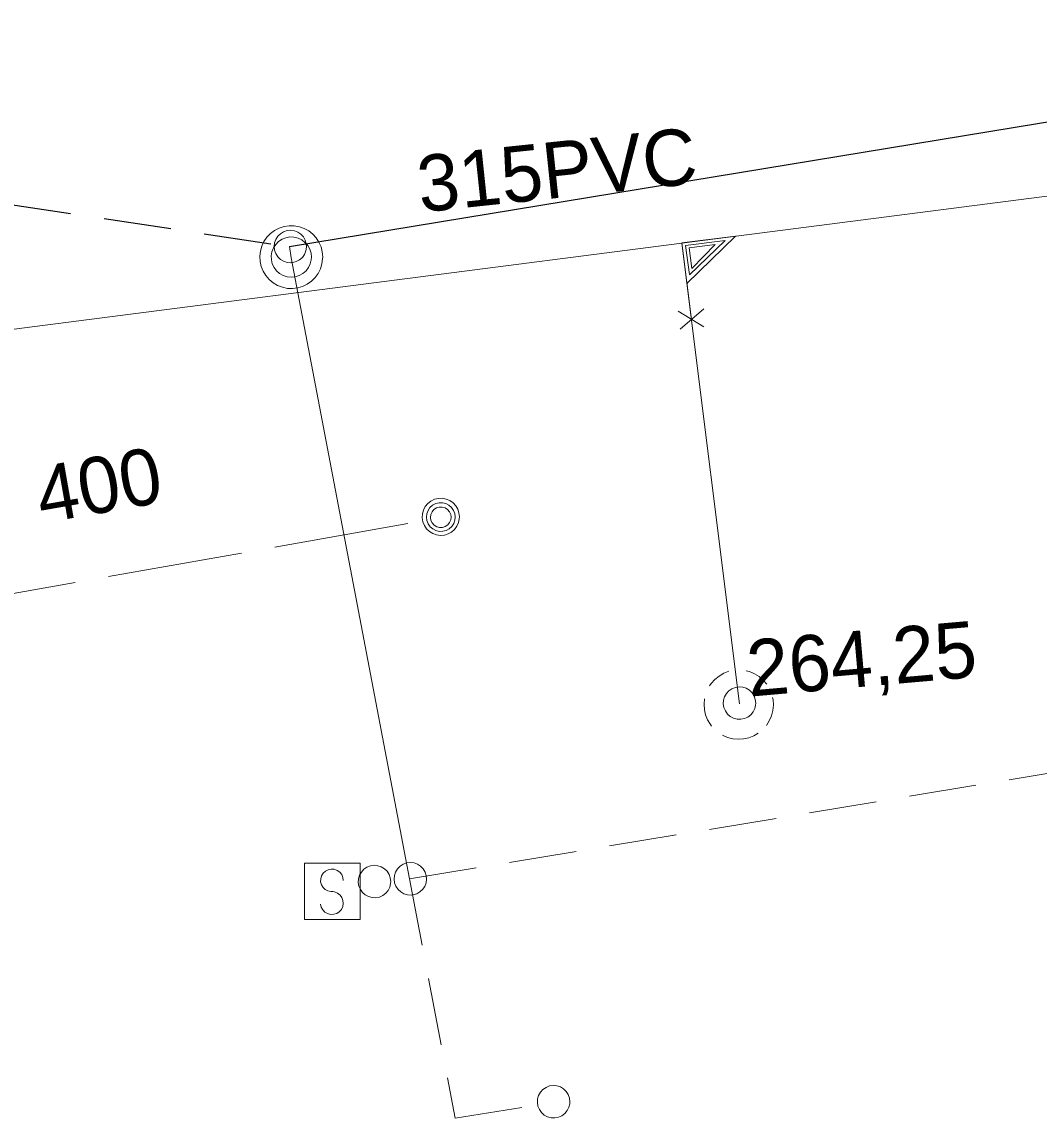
# Model space of a CAD drawing. Extents: x -732096 to -731933, y -1048703 to -1047964.
# Drawn here: x -732052.65 to -732038.19, y -1048400.1 to -1048384.52 of the extents above; entities that cross this region are included whole.
import ezdxf

# ---------------------------------------------------------------- set-up
doc = ezdxf.new("R2010")
doc.units = 0
doc.header["$LTSCALE"] = 0.32
doc.linetypes.add('LONG_DASHED', pattern=[7.5, 6, -1.5])
doc.linetypes.add('MEDIUM_DASHED', pattern=[4.5, 3, -1.5])
doc.layers.add('1', color=7, linetype='Continuous')
for name, color, linetype, lineweight in [('18', 7, 'Continuous', 13), ('20', 7, 'Continuous', 13), ('49', 7, 'Continuous', 13), ('8', 7, 'Continuous', 13)]:
    doc.layers.add(name, color=color, linetype=linetype, lineweight=lineweight)

msp = doc.modelspace()

# ---------------------------------------------------------------- linework, layer by layer
at = {"layer": '18'}
for p, q in [((-732042.954, -1048388.852), (-732043.32, -1048388.628)), ((-732043.29, -1048388.883), (-732042.954, -1048388.594))]:
    msp.add_line(p, q, dxfattribs=at)
for points in [[(-732043.129, -1048388.744), (-732043.269, -1048387.658), (-732042.505, -1048387.56), (-732043.195, -1048388.232)], [(-732043.161, -1048388.107), (-732043.214, -1048387.696), (-732042.652, -1048387.623), (-732043.16, -1048388.109)], [(-732042.602, -1048393.747), (-732042.673, -1048393.775), (-732042.74, -1048393.814), (-732042.8, -1048393.862), (-732042.851, -1048393.919), (-732042.875, -1048393.953)], [(-732042.061, -1048393.93), (-732042.111, -1048393.872), (-732042.169, -1048393.822), (-732042.234, -1048393.781), (-732042.305, -1048393.752), (-732042.354, -1048393.738)], [(-732042.066, -1048394.516), (-732042.025, -1048394.451), (-732041.994, -1048394.381), (-732041.975, -1048394.306), (-732041.967, -1048394.23), (-732041.972, -1048394.153), (-732041.978, -1048394.118)], [(-732042.947, -1048394.139), (-732042.953, -1048394.216), (-732042.948, -1048394.293), (-732042.931, -1048394.368), (-732042.902, -1048394.439), (-732042.862, -1048394.505), (-732042.846, -1048394.527)], [(-732042.689, -1048394.656), (-732042.619, -1048394.687), (-732042.544, -1048394.706), (-732042.468, -1048394.713), (-732042.391, -1048394.708), (-732042.316, -1048394.691), (-732042.244, -1048394.663), (-732042.184, -1048394.628)]]:
    msp.add_lwpolyline(points, dxfattribs=at)
for points in [[(-732043.125, -1048388.019), (-732043.162, -1048387.729), (-732042.793, -1048387.682)], [(-732046.43, -1048391.551), (-732046.436, -1048391.495), (-732046.453, -1048391.442), (-732046.482, -1048391.393), (-732046.52, -1048391.352), (-732046.566, -1048391.32), (-732046.618, -1048391.298), (-732046.673, -1048391.287), (-732046.729, -1048391.289), (-732046.784, -1048391.302), (-732046.835, -1048391.327), (-732046.879, -1048391.362), (-732046.915, -1048391.405), (-732046.94, -1048391.455), (-732046.955, -1048391.51), (-732046.958, -1048391.566), (-732046.949, -1048391.621), (-732046.928, -1048391.674), (-732046.897, -1048391.72), (-732046.857, -1048391.759), (-732046.809, -1048391.789), (-732046.756, -1048391.808), (-732046.7, -1048391.815), (-732046.644, -1048391.811), (-732046.59, -1048391.794), (-732046.541, -1048391.767), (-732046.499, -1048391.729), (-732046.466, -1048391.684), (-732046.443, -1048391.633), (-732046.431, -1048391.578)], [(-732046.489, -1048391.554), (-732046.495, -1048391.505), (-732046.513, -1048391.459), (-732046.541, -1048391.418), (-732046.578, -1048391.385), (-732046.622, -1048391.363), (-732046.67, -1048391.351), (-732046.719, -1048391.351), (-732046.767, -1048391.363), (-732046.811, -1048391.386), (-732046.848, -1048391.419), (-732046.876, -1048391.46), (-732046.893, -1048391.507), (-732046.899, -1048391.556), (-732046.892, -1048391.605), (-732046.874, -1048391.651), (-732046.846, -1048391.691), (-732046.809, -1048391.724), (-732046.765, -1048391.746), (-732046.716, -1048391.758), (-732046.667, -1048391.757), (-732046.619, -1048391.745), (-732046.576, -1048391.721), (-732046.539, -1048391.688), (-732046.511, -1048391.647), (-732046.495, -1048391.6)], [(-732046.548, -1048391.558), (-732046.554, -1048391.516), (-732046.571, -1048391.478), (-732046.599, -1048391.447), (-732046.634, -1048391.424), (-732046.674, -1048391.413), (-732046.716, -1048391.413), (-732046.756, -1048391.425), (-732046.791, -1048391.448), (-732046.818, -1048391.48), (-732046.835, -1048391.518), (-732046.84, -1048391.559), (-732046.834, -1048391.601), (-732046.816, -1048391.638), (-732046.788, -1048391.67), (-732046.752, -1048391.692), (-732046.712, -1048391.703), (-732046.67, -1048391.702), (-732046.63, -1048391.689), (-732046.596, -1048391.666), (-732046.569, -1048391.633), (-732046.553, -1048391.595)], [(-732042.218, -1048394.199), (-732042.224, -1048394.147), (-732042.242, -1048394.097), (-732042.27, -1048394.053), (-732042.308, -1048394.016), (-732042.353, -1048393.989), (-732042.403, -1048393.973), (-732042.455, -1048393.968), (-732042.507, -1048393.975), (-732042.556, -1048393.994), (-732042.6, -1048394.024), (-732042.635, -1048394.063), (-732042.661, -1048394.108), (-732042.676, -1048394.159), (-732042.679, -1048394.211), (-732042.671, -1048394.263), (-732042.65, -1048394.311), (-732042.62, -1048394.354), (-732042.58, -1048394.389), (-732042.534, -1048394.413), (-732042.483, -1048394.427), (-732042.431, -1048394.429), (-732042.379, -1048394.419), (-732042.331, -1048394.397), (-732042.289, -1048394.365), (-732042.256, -1048394.325), (-732042.232, -1048394.278), (-732042.22, -1048394.227)]]:
    msp.add_lwpolyline(points, close=True, dxfattribs=at)
at = {"layer": '20', "linetype": 'LONG_DASHED'}
msp.add_line((-732053.78, -1048392.82), (-732046.694, -1048391.564), dxfattribs=at)
msp.add_line((-732053.78, -1048392.82), (-732046.694, -1048391.564), dxfattribs=at)
at = {"layer": '20'}
msp.add_lwpolyline([(-732058.87, -1048389.67), (-732043.269, -1048387.661), (-732032.557, -1048386.281), (-732028.59, -1048385.77)], dxfattribs=at)
msp.add_lwpolyline([(-732058.87, -1048389.67), (-732043.269, -1048387.661), (-732032.557, -1048386.281), (-732028.59, -1048385.77)], dxfattribs=at)
at = {"layer": '49'}
msp.add_line((-732042.449, -1048394.21), (-732043.269, -1048387.661), dxfattribs=at)
msp.add_line((-732042.449, -1048394.21), (-732043.269, -1048387.661), dxfattribs=at)
at = {"layer": '8', "lineweight": 25}
msp.add_line((-732048.844, -1048387.71), (-732024.987, -1048383.778), dxfattribs=at)
at = {"layer": '8', "linetype": 'MEDIUM_DASHED', "lineweight": 25}
msp.add_line((-732054.329, -1048386.88), (-732048.844, -1048387.71), dxfattribs=at)
at = {"layer": '8'}
for points in [[(-732048.372, -1048387.859), (-732048.379, -1048387.786), (-732048.397, -1048387.715), (-732048.426, -1048387.648), (-732048.465, -1048387.587), (-732048.514, -1048387.532), (-732048.571, -1048387.487), (-732048.636, -1048387.452), (-732048.705, -1048387.427), (-732048.777, -1048387.414), (-732048.85, -1048387.413), (-732048.923, -1048387.424), (-732048.992, -1048387.447), (-732049.056, -1048387.48), (-732049.115, -1048387.524), (-732049.166, -1048387.577), (-732049.208, -1048387.637), (-732049.239, -1048387.704), (-732049.259, -1048387.774), (-732049.267, -1048387.847), (-732049.262, -1048387.92), (-732049.247, -1048387.991), (-732049.22, -1048388.059), (-732049.181, -1048388.122), (-732049.134, -1048388.177), (-732049.078, -1048388.224), (-732049.014, -1048388.261), (-732048.946, -1048388.288), (-732048.875, -1048388.303), (-732048.801, -1048388.306), (-732048.728, -1048388.297), (-732048.659, -1048388.276), (-732048.593, -1048388.244), (-732048.532, -1048388.202), (-732048.48, -1048388.151), (-732048.438, -1048388.091), (-732048.404, -1048388.026), (-732048.384, -1048387.956), (-732048.374, -1048387.884)], [(-732048.534, -1048387.859), (-732048.539, -1048387.801), (-732048.558, -1048387.745), (-732048.585, -1048387.694), (-732048.625, -1048387.65), (-732048.671, -1048387.614), (-732048.723, -1048387.589), (-732048.781, -1048387.575), (-732048.84, -1048387.573), (-732048.897, -1048387.583), (-732048.951, -1048387.605), (-732049, -1048387.637), (-732049.041, -1048387.678), (-732049.073, -1048387.727), (-732049.095, -1048387.782), (-732049.105, -1048387.839), (-732049.103, -1048387.898), (-732049.09, -1048387.955), (-732049.065, -1048388.008), (-732049.029, -1048388.054), (-732048.985, -1048388.093), (-732048.933, -1048388.121), (-732048.877, -1048388.139), (-732048.82, -1048388.145), (-732048.762, -1048388.139), (-732048.706, -1048388.122), (-732048.654, -1048388.093), (-732048.61, -1048388.054), (-732048.576, -1048388.008), (-732048.551, -1048387.955), (-732048.536, -1048387.898)], [(-732048.799, -1048387.936), (-732048.748, -1048387.923), (-732048.701, -1048387.897), (-732048.662, -1048387.863), (-732048.631, -1048387.82), (-732048.611, -1048387.771), (-732048.603, -1048387.72), (-732048.606, -1048387.667), (-732048.62, -1048387.617), (-732048.646, -1048387.571), (-732048.683, -1048387.532), (-732048.726, -1048387.504), (-732048.775, -1048387.485), (-732048.828, -1048387.477), (-732048.879, -1048387.482), (-732048.93, -1048387.498), (-732048.974, -1048387.526), (-732049.012, -1048387.562), (-732049.041, -1048387.607), (-732049.057, -1048387.656), (-732049.064, -1048387.708), (-732049.058, -1048387.76), (-732049.04, -1048387.81), (-732049.011, -1048387.854), (-732048.973, -1048387.891), (-732048.929, -1048387.918), (-732048.879, -1048387.934), (-732048.827, -1048387.939)], [(-732048.63, -1048396.475), (-732047.841, -1048396.475), (-732047.841, -1048397.275), (-732048.63, -1048397.275)], [(-732047.406, -1048396.736), (-732047.412, -1048396.684), (-732047.429, -1048396.634), (-732047.458, -1048396.59), (-732047.496, -1048396.553), (-732047.541, -1048396.526), (-732047.591, -1048396.51), (-732047.643, -1048396.505), (-732047.695, -1048396.512), (-732047.744, -1048396.531), (-732047.788, -1048396.561), (-732047.823, -1048396.6), (-732047.849, -1048396.645), (-732047.864, -1048396.696), (-732047.867, -1048396.748), (-732047.858, -1048396.8), (-732047.838, -1048396.848), (-732047.808, -1048396.891), (-732047.768, -1048396.926), (-732047.722, -1048396.95), (-732047.671, -1048396.964), (-732047.619, -1048396.966), (-732047.567, -1048396.956), (-732047.519, -1048396.934), (-732047.477, -1048396.902), (-732047.444, -1048396.862), (-732047.42, -1048396.815), (-732047.407, -1048396.764)], [(-732047.088, -1048396.924), (-732047.037, -1048396.909), (-732046.991, -1048396.883), (-732046.953, -1048396.848), (-732046.923, -1048396.804), (-732046.904, -1048396.755), (-732046.897, -1048396.703), (-732046.901, -1048396.651), (-732046.916, -1048396.601), (-732046.944, -1048396.556), (-732046.981, -1048396.518), (-732047.025, -1048396.49), (-732047.074, -1048396.472), (-732047.127, -1048396.466), (-732047.178, -1048396.472), (-732047.228, -1048396.489), (-732047.272, -1048396.518), (-732047.309, -1048396.555), (-732047.337, -1048396.6), (-732047.353, -1048396.65), (-732047.358, -1048396.702), (-732047.351, -1048396.754), (-732047.332, -1048396.803), (-732047.302, -1048396.847), (-732047.263, -1048396.883), (-732047.218, -1048396.908), (-732047.168, -1048396.924), (-732047.115, -1048396.927)], [(-732044.86, -1048399.866), (-732044.867, -1048399.814), (-732044.884, -1048399.764), (-732044.913, -1048399.72), (-732044.951, -1048399.683), (-732044.995, -1048399.656), (-732045.046, -1048399.64), (-732045.098, -1048399.635), (-732045.149, -1048399.642), (-732045.198, -1048399.661), (-732045.242, -1048399.691), (-732045.277, -1048399.73), (-732045.304, -1048399.775), (-732045.318, -1048399.826), (-732045.321, -1048399.878), (-732045.313, -1048399.93), (-732045.293, -1048399.978), (-732045.262, -1048400.021), (-732045.223, -1048400.056), (-732045.176, -1048400.08), (-732045.125, -1048400.094), (-732045.073, -1048400.096), (-732045.022, -1048400.086), (-732044.973, -1048400.064), (-732044.931, -1048400.032), (-732044.899, -1048399.992), (-732044.875, -1048399.945), (-732044.862, -1048399.894)]]:
    msp.add_lwpolyline(points, close=True, dxfattribs=at)
for points in [[(-732048.844, -1048387.71), (-732048.82, -1048387.87), (-732047.138, -1048396.699)], [(-732048.081, -1048396.721), (-732048.087, -1048396.678), (-732048.103, -1048396.637), (-732048.13, -1048396.603), (-732048.167, -1048396.577), (-732048.208, -1048396.562), (-732048.251, -1048396.559), (-732048.294, -1048396.567), (-732048.333, -1048396.587), (-732048.366, -1048396.616), (-732048.389, -1048396.654), (-732048.401, -1048396.696), (-732048.402, -1048396.739), (-732048.39, -1048396.782), (-732048.368, -1048396.819), (-732048.336, -1048396.85), (-732048.298, -1048396.87), (-732048.255, -1048396.879), (-732048.228, -1048396.879)], [(-732048.404, -1048397.058), (-732048.394, -1048397.101), (-732048.372, -1048397.14), (-732048.341, -1048397.171), (-732048.303, -1048397.192), (-732048.26, -1048397.203), (-732048.216, -1048397.201), (-732048.174, -1048397.188), (-732048.137, -1048397.164), (-732048.108, -1048397.131), (-732048.089, -1048397.091), (-732048.081, -1048397.048), (-732048.085, -1048397.004), (-732048.101, -1048396.963), (-732048.127, -1048396.928), (-732048.162, -1048396.901), (-732048.203, -1048396.884), (-732048.228, -1048396.879)]]:
    msp.add_lwpolyline(points, dxfattribs=at)
at = {"layer": '8', "linetype": 'MEDIUM_DASHED'}
for points in [[(-732047.138, -1048396.699), (-732033.763, -1048394.486), (-732033.366, -1048396.867)], [(-732047.138, -1048396.699), (-732046.491, -1048400.098), (-732045.092, -1048399.877)]]:
    msp.add_lwpolyline(points, dxfattribs=at)

# ---------------------------------------------------------------- texts
at = {"layer": '1'}
for s, rotation, p in [('315PVC', 6, (-732046.984, -1048387.224)), ('400 ', 10, (-732052.366, -1048391.646)), ('264,25', 5, (-732042.309, -1048394.108))]:
    msp.add_text(s, height=0.8, rotation=rotation, dxfattribs=at).set_placement(p)

doc.saveas('drawing.dxf')
